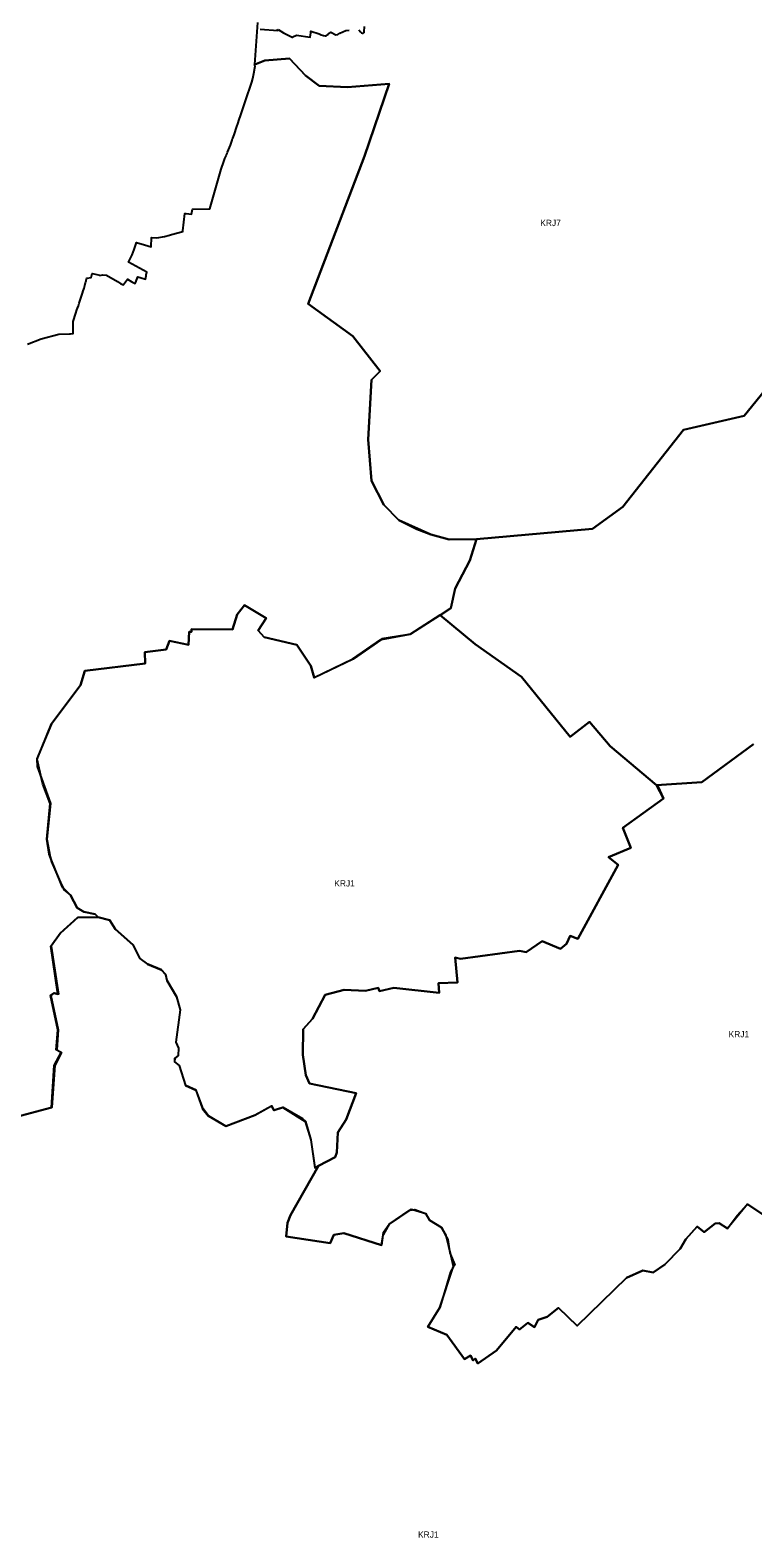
# Model space of a CAD drawing. Extents: x -563112 to -465432, y -1206259 to -1132144.
# Drawn here: x -547208 to -541465, y -1163011 to -1151020 of the extents above; entities that cross this region are included whole.
import ezdxf

# ---------------------------------------------------------------- set-up
doc = ezdxf.new("R2010")
doc.units = 0
doc.layers.add('krajiny', color=7, linetype='Continuous')

msp = doc.modelspace()

# ---------------------------------------------------------------- linework, layer by layer
at = {"layer": 'krajiny'}
for points in [[(-541107.03, -1153561.03), (-541534.8, -1154087.13), (-542016.86, -1154198.37), (-542498.93, -1154810.22), (-542739.96, -1154986.35), (-543661.43, -1155067.77), (-543877.06, -1155069.86), (-544022.43, -1155031.37), (-544277.27, -1154915.88), (-544396.99, -1154796.12), (-544495.33, -1154603.65), (-544521.63, -1154274.3), (-544495.33, -1153799.54), (-544427.65, -1153730.69), (-544643.75, -1153452.85), (-544998.78, -1153195.58), (-544551.14, -1152022.86), (-544355.62, -1151446.4), (-544684.92, -1151472.13), (-544911.31, -1151461.84), (-545019.36, -1151379.49), (-545147.99, -1151245.66), (-545343.51, -1151261.11), (-545423.39, -1151292.93), (-545398.19, -1150957.61)], [(-545381.24, -1151010.83), (-545238.51, -1151021.15), (-545246.64, -1151014.94)], [(-545237.67, -1151013.97), (-545195.97, -1151040.02), (-545167.69, -1151054.76), (-545146.01, -1151064.93), (-545125.62, -1151074.91), (-545121.27, -1151074.07), (-545120.38, -1151072.47), (-545091.15, -1151058.89), (-544982.63, -1151074.88), (-544977.9, -1151041.47), (-544977.34, -1151037.5), (-544977.23, -1151036.77), (-544976.58, -1151032.15), (-544976.45, -1151028.55), (-544910.38, -1151049.91), (-544894.62, -1151057.09), (-544877.39, -1151062.78), (-544864.2, -1151064.85), (-544856.53, -1151063.98), (-544844.61, -1151057.22), (-544836.94, -1151046.94), (-544819.14, -1151035.24), (-544778.03, -1151057.66), (-544761.6, -1151053.95), (-544746.73, -1151043.97), (-544698.76, -1151022.98), (-544673.39, -1151019.02)], [(-544596.45, -1151017.9), (-544583.69, -1151033.44), (-544574.77, -1151041.7), (-544566.94, -1151044.29), (-544560.43, -1151043.82), (-544553.7, -1151037.15), (-544553.55, -1151033.12), (-544551.1, -1150991.78)], [(-547228.51, -1153516.45), (-547121.68, -1153474.54), (-546980.47, -1153437.1), (-546895.43, -1153434.32), (-546887.6, -1153434.49), (-546867.37, -1153433.4), (-546865.7, -1153337.57), (-546844.71, -1153270.62), (-546844.44, -1153269.8), (-546836.06, -1153245.02), (-546831.6, -1153231.85), (-546824.71, -1153211.67), (-546817.46, -1153189.84), (-546810.09, -1153167.63), (-546807.5, -1153159.83), (-546804.86, -1153151.87), (-546802.54, -1153144.47), (-546795.02, -1153120.52), (-546792.28, -1153111.8), (-546789.69, -1153102.43), (-546788.94, -1153100.16), (-546779.19, -1153070.64), (-546773.39, -1153049.45), (-546767.38, -1153027.48), (-546764.25, -1153016.04), (-546762.7, -1153010.42), (-546759.22, -1152997.85), (-546757.65, -1152992.84), (-546724.08, -1152987.11), (-546715.68, -1152954.63), (-546702.53, -1152957.44), (-546654.08, -1152967.8), (-546653.4, -1152970.34), (-546630.18, -1152966.44), (-546601.24, -1152968.01), (-546514.2, -1153018.23), (-546486.46, -1153036.61), (-546467.28, -1153045.3), (-546465.61, -1153043.18), (-546434.83, -1153000.15), (-546398.98, -1153022.11), (-546374.51, -1153035.71), (-546369.42, -1153023.34), (-546363.61, -1153009.11), (-546352.52, -1152981.66), (-546326.93, -1152989.9), (-546291.72, -1152999.98), (-546289.34, -1152986.07), (-546287.05, -1152972.74), (-546285.51, -1152963.77), (-546284.67, -1152958.69), (-546282.1, -1152943.15), (-546427.61, -1152865.85), (-546397.09, -1152806.23), (-546382.23, -1152765.05), (-546364.2, -1152707.81), (-546300.47, -1152727.31), (-546246.06, -1152741.87), (-546243, -1152669.3), (-546201.49, -1152671.33), (-546141.42, -1152659.52), (-546101.57, -1152649.21), (-546083.81, -1152643.85), (-545995.07, -1152619.71), (-545994.7, -1152616.98), (-545994.47, -1152614.44), (-545978.71, -1152476.62), (-545966.94, -1152478.33), (-545926.37, -1152484.22), (-545918.74, -1152444.02), (-545778.94, -1152440.15), (-545691.01, -1152125.35), (-545668.88, -1152062.91), (-545659.91, -1152040.78), (-545655.51, -1152029.92), (-545653.93, -1152026.02), (-545649.27, -1152014.54), (-545647.83, -1152010.98), (-545643.2, -1151999.55), (-545639.07, -1151989.37), (-545632.16, -1151972.33), (-545616.87, -1151934.6), (-545616.4, -1151933.43), (-545613.81, -1151927.06), (-545601.94, -1151893.42), (-545601.58, -1151892.4), (-545599.88, -1151887.59), (-545598.63, -1151884.05), (-545596.99, -1151879.41), (-545587.06, -1151851.28), (-545578.84, -1151828), (-545576.52, -1151821.42), (-545574.91, -1151816.87), (-545567.7, -1151795.13), (-545562.17, -1151778.48), (-545559.84, -1151771.45), (-545555.34, -1151757.91), (-545548.76, -1151738.09), (-545534.01, -1151693.64), (-545515.65, -1151638.33), (-545504.73, -1151605.43), (-545483.62, -1151541.82), (-545459.21, -1151471.92), (-545445.56, -1151432.84), (-545439.54, -1151403.64), (-545431.41, -1151364.18), (-545431.24, -1151363.35), (-545423.77, -1151319.26), (-545422.93, -1151314.27), (-545422.82, -1151313.65), (-545420.31, -1151312), (-545423.02, -1151301.8), (-545423.96, -1151298.24), (-545423.39, -1151292.93), (-545343.51, -1151261.11), (-545147.99, -1151245.66), (-545019.36, -1151379.49), (-544911.31, -1151461.84), (-544684.92, -1151472.13), (-544355.62, -1151446.4), (-544551.14, -1152022.86), (-544998.78, -1153195.58), (-544643.75, -1153452.85), (-544427.65, -1153730.69), (-544495.33, -1153799.54), (-544521.63, -1154274.3), (-544495.33, -1154603.65), (-544396.99, -1154796.12), (-544277.27, -1154915.88), (-544136.17, -1154988.6), (-544022.43, -1155031.37), (-543877.06, -1155069.86), (-543661.43, -1155067.77), (-543713.59, -1155237.09), (-543829.47, -1155461.15), (-543865.83, -1155616.73), (-543949.82, -1155671.23), (-544186.19, -1155824.58), (-544231.08, -1155832.02), (-544411.85, -1155861.99), (-544416.18, -1155865), (-544642.28, -1156022.09), (-544950.92, -1156169.74), (-544951.12, -1156169.03), (-544977.35, -1156075.27), (-545088.26, -1155909.71), (-545349.53, -1155846.76), (-545397.19, -1155794.01), (-545332.29, -1155696.63), (-545505.02, -1155593.54), (-545563.98, -1155666.69), (-545600.5, -1155787.75), (-545925.85, -1155784.29), (-545926.89, -1155805.09), (-545944.27, -1155803.99), (-545949.04, -1155907.31), (-546101.57, -1155876.72), (-546128.03, -1155944.88), (-546295.42, -1155967.55), (-546295.21, -1156056.71), (-546772.54, -1156115.58), (-546808.05, -1156229.34), (-547038.5, -1156536.65), (-547155.79, -1156816.16), (-547153.21, -1156876.84), (-547118.21, -1156972.93), (-547046.75, -1157169.14), (-547075.67, -1157453.12), (-547047.99, -1157593.37), (-547039.73, -1157635.22), (-546958.28, -1157816.75), (-546946.78, -1157842.38), (-546940.07, -1157857.35), (-546887.52, -1157900.73), (-546834.23, -1158000.75), (-546782.18, -1158031.75), (-546690.87, -1158050.37), (-546666.54, -1158073.94), (-546669.37, -1158074.01), (-546828.9, -1158078.03), (-546967.55, -1158201.41), (-547040.15, -1158304.51), (-546983.8, -1158687.23), (-546987, -1158686.42), (-547017.88, -1158678.61), (-547018.65, -1158679.19), (-547042.5, -1158697.31), (-546984.51, -1158970.05), (-546997.27, -1159130.19), (-546958.72, -1159151.86), (-547012.95, -1159253.1), (-547036.28, -1159588.59), (-547443.9, -1159698.04)], [(-541459.18, -1156697.45), (-541871.07, -1157000.08), (-542229.69, -1157024.7), (-542598.97, -1156713.31), (-542762.49, -1156520.37), (-542916.64, -1156640.19), (-543303.6, -1156163.18), (-543670.51, -1155904.05), (-543949.82, -1155671.23), (-543865.83, -1155616.73), (-543829.47, -1155461.15), (-543713.59, -1155237.09), (-543661.43, -1155067.77), (-542739.96, -1154986.35), (-542498.93, -1154810.22), (-542016.86, -1154198.37), (-541534.8, -1154087.13), (-541107.03, -1153561.03)], [(-541353.16, -1160459.78), (-541505.92, -1160357.38), (-541666.93, -1160551.6), (-541732.22, -1160507.9), (-541764.41, -1160511.13), (-541851.21, -1160580.02), (-541907.32, -1160534.45), (-541997.8, -1160634.79), (-542042.38, -1160713.32), (-542164.49, -1160838.25), (-542257.52, -1160900.82), (-542339.71, -1160883.72), (-542468.77, -1160942.5), (-542859.71, -1161325.19), (-543008.34, -1161180.62), (-543099.61, -1161253.03), (-543169.72, -1161276.81), (-543198.88, -1161336.81), (-543252.31, -1161300.43), (-543319.79, -1161354.02), (-543345.56, -1161333.75), (-543502.52, -1161521.46), (-543650.81, -1161625.69), (-543670.33, -1161585.02), (-543686.74, -1161601.87), (-543707.7, -1161561.87), (-543755.31, -1161588.93), (-543895.68, -1161397.51), (-544046.92, -1161331.98), (-543952.04, -1161178.78), (-543845.04, -1160857.86), (-543843.25, -1160852.5), (-543862.69, -1160770.47), (-543880.88, -1160693.73), (-543898.24, -1160620.46), (-543901.65, -1160606.09), (-543939.83, -1160542.49), (-544033.71, -1160484.97), (-544058.42, -1160436.97), (-544064.23, -1160435.16), (-544170.52, -1160402.1), (-544180.03, -1160399.14), (-544190.19, -1160405.94), (-544353.93, -1160515.42), (-544401.98, -1160599.92), (-544404.24, -1160603.9), (-544414.64, -1160683.03), (-544714.94, -1160586.99), (-544793.56, -1160601.36), (-544822.87, -1160666.09), (-545173.19, -1160613.29), (-545162, -1160505.35), (-545139.43, -1160444.89), (-544915.64, -1160053.09), (-544784.74, -1159984.38), (-544770.06, -1159945.82), (-544761.67, -1159788.2), (-544697.75, -1159684.69), (-544617.34, -1159475.6), (-544989.17, -1159397.83), (-545017.79, -1159330.74), (-545040.92, -1159168.55), (-545037.49, -1158964.25), (-544963.06, -1158884.45), (-544863.89, -1158693.01), (-544713.65, -1158653.08), (-544542.6, -1158660.99), (-544442.81, -1158636.49), (-544431.81, -1158663.83), (-544317.67, -1158635.41), (-543956.88, -1158676.11), (-543963.23, -1158598.52), (-543811.58, -1158593.68), (-543829.71, -1158394.08), (-543787.42, -1158406.35), (-543319.43, -1158341.45), (-543265.06, -1158352.04), (-543137.75, -1158265.17), (-542992.14, -1158326.22), (-542946.54, -1158286.39), (-542917.05, -1158223.12), (-542854.8, -1158246.08), (-542536.12, -1157658.16), (-542611.58, -1157596.77), (-542433.51, -1157522.37), (-542499.01, -1157365.3), (-542175.91, -1157131.68), (-542229.69, -1157024.7), (-541871.07, -1157000.08), (-541459.18, -1156697.45)], [(-547446.98, -1159698.04), (-547039.36, -1159588.59), (-547016.03, -1159253.1), (-546961.8, -1159151.86), (-547000.35, -1159130.19), (-546987.59, -1158970.05), (-547045.58, -1158697.31), (-547020.96, -1158678.61), (-547018.65, -1158679.19), (-546986.88, -1158687.23), (-546987, -1158686.42), (-547043.23, -1158304.51), (-546970.63, -1158201.41), (-546831.98, -1158078.03), (-546669.62, -1158073.94), (-546669.37, -1158074.01), (-546578.08, -1158099.71), (-546531.59, -1158168.76), (-546392.9, -1158294.14), (-546336.01, -1158401.96), (-546275.25, -1158448.18), (-546166.07, -1158492.63), (-546132.72, -1158531.54), (-546122.67, -1158577.51), (-546044.91, -1158708.41), (-546017.11, -1158811.14), (-546051.59, -1159069.95), (-546030.36, -1159116.1), (-546031.7, -1159174.41), (-546059.85, -1159199.87), (-546060.3, -1159224.32), (-546023.86, -1159254.16), (-545974.67, -1159412.49), (-545891.85, -1159449.97), (-545837.36, -1159597.8), (-545792.95, -1159654.14), (-545653.63, -1159737.86), (-545651.76, -1159737.14), (-545421.8, -1159648.22), (-545290.89, -1159575.18), (-545290.18, -1159576.5), (-545272.25, -1159610.02), (-545269.59, -1159609.23), (-545201.43, -1159589), (-545200.43, -1159589.62), (-545021.54, -1159699.53), (-544978.07, -1159844.92), (-544945.94, -1160067.37), (-544943.08, -1160065.87), (-544914.36, -1160050.8), (-544915.67, -1160053.1), (-545139.43, -1160444.89), (-545162, -1160505.35), (-545173.19, -1160613.29), (-544822.87, -1160666.09), (-544793.56, -1160601.36), (-544714.94, -1160586.99), (-544414.64, -1160683.03), (-544401.98, -1160599.92), (-544398.92, -1160579.85), (-544353.93, -1160515.42), (-544303.3, -1160481.28), (-544194.83, -1160406.84), (-544190.19, -1160405.94), (-544170.52, -1160402.1), (-544151.29, -1160398.35), (-544066.3, -1160431.78), (-544064.23, -1160435.16), (-544033.71, -1160484.97), (-543939.83, -1160542.49), (-543898.24, -1160620.46), (-543888.99, -1160637.81), (-543880.88, -1160693.73), (-543873.56, -1160744.19), (-543862.69, -1160770.47), (-543834.25, -1160839.24), (-543845.04, -1160857.86), (-543866.61, -1160895.1), (-543905.91, -1161030.46), (-543952.04, -1161178.78), (-544046.92, -1161331.98), (-543895.68, -1161397.51), (-543755.31, -1161588.93), (-543707.7, -1161561.87), (-543686.74, -1161601.87), (-543670.33, -1161585.02), (-543650.81, -1161625.69), (-543502.52, -1161521.46), (-543345.56, -1161333.75), (-543319.79, -1161354.02), (-543252.31, -1161300.43), (-543198.88, -1161336.81), (-543169.72, -1161276.81), (-543099.61, -1161253.03), (-543008.34, -1161180.62), (-542859.71, -1161325.19), (-542468.77, -1160942.5), (-542339.71, -1160883.72), (-542257.52, -1160900.82), (-542164.49, -1160838.25), (-542042.38, -1160713.32), (-541997.8, -1160634.79), (-541907.32, -1160534.45), (-541851.21, -1160580.02), (-541764.41, -1160511.13), (-541732.22, -1160507.9), (-541666.93, -1160551.6), (-541588.14, -1160447.79), (-541505.92, -1160357.38), (-541353.16, -1160459.78)]]:
    msp.add_lwpolyline(points, dxfattribs=at)
msp.add_lwpolyline([(-545332.29, -1155696.63), (-545397.19, -1155794.01), (-545349.53, -1155846.76), (-545088.26, -1155909.71), (-544977.35, -1156075.27), (-544951.18, -1156169.06), (-544951.12, -1156169.03), (-544643.27, -1156020.99), (-544421.97, -1155866.03), (-544416.18, -1155865), (-544231.08, -1155832.02), (-544186.67, -1155824.11), (-543950.6, -1155670.58), (-543949.82, -1155671.23), (-543670.51, -1155904.05), (-543303.6, -1156163.18), (-542916.64, -1156640.19), (-542762.49, -1156520.37), (-542598.97, -1156713.31), (-542229.69, -1157024.7), (-542220.26, -1157032.65), (-542175.91, -1157131.68), (-542499.01, -1157365.3), (-542433.51, -1157522.37), (-542611.58, -1157596.77), (-542536.12, -1157658.16), (-542854.8, -1158246.08), (-542917.05, -1158223.12), (-542946.54, -1158286.39), (-542992.14, -1158326.22), (-543137.75, -1158265.17), (-543265.06, -1158352.04), (-543319.43, -1158341.45), (-543787.42, -1158406.35), (-543829.71, -1158394.08), (-543811.58, -1158593.68), (-543963.23, -1158598.52), (-543956.88, -1158676.11), (-544317.67, -1158635.41), (-544431.81, -1158663.83), (-544442.81, -1158636.49), (-544542.6, -1158660.99), (-544713.65, -1158653.08), (-544863.89, -1158693.01), (-544963.06, -1158884.45), (-545037.49, -1158964.25), (-545040.92, -1159168.55), (-545017.79, -1159330.74), (-544989.17, -1159397.83), (-544617.34, -1159475.6), (-544697.75, -1159684.69), (-544761.67, -1159788.2), (-544770.06, -1159945.82), (-544784.74, -1159984.38), (-544915.67, -1160053.1), (-544942.86, -1160067.37), (-544943.08, -1160065.87), (-544974.99, -1159844.92), (-545018.46, -1159699.53), (-545040.02, -1159679.53), (-545198.35, -1159589), (-545200.43, -1159589.62), (-545269.17, -1159610.02), (-545269.59, -1159609.23), (-545287.81, -1159575.18), (-545290.18, -1159576.5), (-545418.72, -1159648.22), (-545650.55, -1159737.86), (-545651.76, -1159737.14), (-545789.87, -1159654.14), (-545834.28, -1159597.8), (-545888.77, -1159449.97), (-545971.59, -1159412.49), (-546020.78, -1159254.16), (-546057.22, -1159224.32), (-546056.77, -1159199.87), (-546028.62, -1159174.41), (-546027.28, -1159116.1), (-546048.51, -1159069.95), (-546014.03, -1158811.14), (-546041.83, -1158708.41), (-546119.59, -1158577.51), (-546129.64, -1158531.54), (-546162.99, -1158492.63), (-546272.17, -1158448.18), (-546332.93, -1158401.96), (-546389.82, -1158294.14), (-546528.51, -1158168.76), (-546575, -1158099.71), (-546666.54, -1158073.94), (-546690.87, -1158050.37), (-546782.18, -1158031.75), (-546834.23, -1158000.75), (-546887.52, -1157900.73), (-546946.78, -1157842.38), (-546948.78, -1157840.42), (-546958.28, -1157816.75), (-547047.99, -1157593.37), (-547055.76, -1157574.02), (-547075.67, -1157453.12), (-547047.87, -1157170.68), (-547108.22, -1157017.8), (-547118.21, -1156972.93), (-547152.63, -1156818.38), (-547038.5, -1156536.65), (-546808.05, -1156229.34), (-546772.54, -1156115.58), (-546295.21, -1156056.71), (-546295.42, -1155967.55), (-546128.03, -1155944.88), (-546101.57, -1155876.72), (-545949.04, -1155907.31), (-545944.27, -1155803.99), (-545926.89, -1155805.09), (-545925.85, -1155784.29), (-545600.5, -1155787.75), (-545563.98, -1155666.69), (-545505.02, -1155593.54)], close=True, dxfattribs=at)

# ---------------------------------------------------------------- texts
for s, p in [('KRJ7', (-543153.97, -1152577.88)), ('KRJ1', (-544791.15, -1157830.46)), ('KRJ1', (-541657.49, -1159030.38)), ('KRJ1', (-544125.43, -1163010.47))]:
    msp.add_text(s, height=50, dxfattribs=at).set_placement(p)

doc.saveas('drawing.dxf')
